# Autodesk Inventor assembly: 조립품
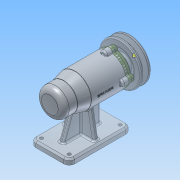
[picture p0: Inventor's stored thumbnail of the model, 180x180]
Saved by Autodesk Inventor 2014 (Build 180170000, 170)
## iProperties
Created: 2019-07
Part Number: 조립품
Document SubType Name: Assembly
Designer: net
Author: net
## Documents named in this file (12)
- C:\Users\net\Desktop\490704V1069\조립품.iam
- C:\Users\net\Desktop\490704V1069\본체.ipt
- C:\Users\net\Desktop\490704V1069\축.ipt
- C:\Users\net\Desktop\490704V1069\베어링 6004.ipt
- C:\Users\net\Desktop\490704V1069\어댑터슬리브.ipt
- C:\Users\net\Desktop\490704V1069\볼트 M4.ipt
- C:\Users\net\Desktop\490704V1069\베어링 51202.ipt
- C:\Users\net\Desktop\490704V1069\커버.ipt
- C:\Users\net\Desktop\490704V1069\키 5 x 5 x 16.ipt
- C:\Users\net\Desktop\490704V1069\오일 실.ipt
- C:\Users\net\Desktop\490704V1069\V벨트풀리.ipt
- C:\Users\net\Desktop\490704V1069\멈춤나사 M3.ipt
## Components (1 placed, 1 different names)
1. V벨트풀리:1
